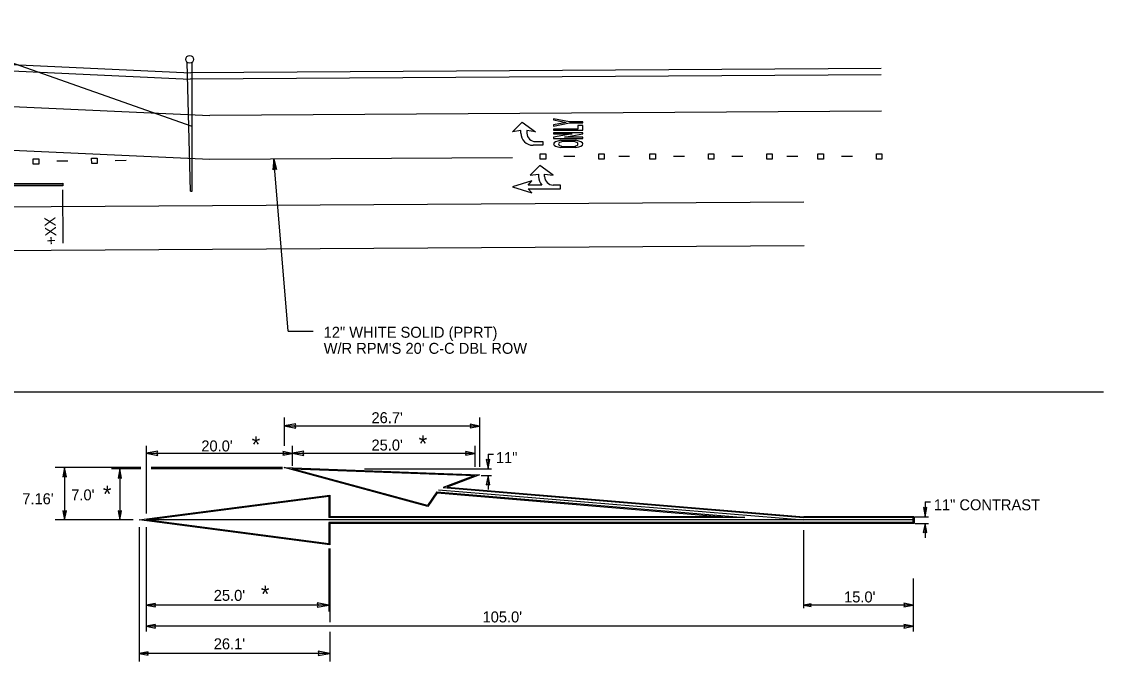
# Model space of a CAD drawing. Extents: x 538465 to 539103, y 1527987 to 1528392.
# Drawn here: x 538806.8 to 539102.9, y 1528140.9 to 1528316.1 of the extents above; entities that cross this region are included whole.
import ezdxf

# ---------------------------------------------------------------- set-up
doc = ezdxf.new("R2010")
doc.units = 0
for name, color, linetype in [('1', 7, 'Continuous'), ('CL_dp', 7, 'Continuous'), ('Default', 7, 'Continuous'), ('DimLines_dp', 7, 'Continuous'), ('DirArrowsPavt', 7, 'Continuous'), ('ImageAttachment_dp', 7, 'Continuous'), ('LeaderLine_dp', 7, 'Continuous'), ('PavtMessage', 7, 'Continuous'), ('PavtMiscMat', 7, 'Continuous'), ('PMStripe6W(10-30)', 7, 'Continuous'), ('TextLabel', 7, 'Continuous'), ('TextMajor', 7, 'Continuous')]:
    doc.layers.add(name, color=color, linetype=linetype)

msp = doc.modelspace()

# ---------------------------------------------------------------- linework, layer by layer
at = {"layer": '1'}
for p, q in [((538852.98, 1528269.7), (538852.08, 1528304.95)), ((538853.51, 1528269.71), (538853.51, 1528304.97)), ((538852.98, 1528269.7), (538853.51, 1528269.71))]:
    msp.add_line(p, q, dxfattribs=at)
msp.add_circle((538852.78, 1528305.76), 1.07, dxfattribs=at)
at = {"layer": 'CL_dp'}
for p, q in [((538611.16, 1528270.2), (538818.07, 1528271.49)), ((538920.87, 1528187.94), (539020.82, 1528179.64)), ((539050.87, 1528179.64), (538840.87, 1528179.64))]:
    msp.add_line(p, q, dxfattribs=at)
at = {"layer": 'Default'}
for p, q in [((538550.39, 1528316.09), (538853.15, 1528302.11)), ((538549.84, 1528314.35), (538852.95, 1528300.36)), ((538547.55, 1528304.74), (538858.35, 1528290.39)), ((538547.91, 1528292.72), (538858.28, 1528278.39)), ((539042.15, 1528291.54), (538858.35, 1528290.39)), ((538858.28, 1528278.39), (538941.21, 1528278.91)), ((538958.24, 1528279.14), (538955.24, 1528279.14)), ((538973.24, 1528279.14), (538970.24, 1528279.14)), ((538988.24, 1528279.14), (538985.24, 1528279.14)), ((539004.24, 1528279.14), (539001.24, 1528279.14)), ((539019.24, 1528279.14), (539016.24, 1528279.14)), ((539034.24, 1528279.14), (539031.24, 1528279.14)), ((538819.42, 1528277.88), (538816.42, 1528277.85)), ((538835.41, 1528278.06), (538832.41, 1528278.02))]:
    msp.add_line(p, q, dxfattribs=at)
for points in [[(538948.78, 1528279.89), (538950.28, 1528279.89), (538950.28, 1528278.39), (538948.78, 1528278.39)], [(538964.78, 1528279.89), (538966.28, 1528279.89), (538966.28, 1528278.39), (538964.78, 1528278.39)], [(538978.78, 1528279.89), (538980.28, 1528279.89), (538980.28, 1528278.39), (538978.78, 1528278.39)], [(538994.78, 1528279.89), (538996.28, 1528279.89), (538996.28, 1528278.39), (538994.78, 1528278.39)], [(539010.78, 1528279.89), (539012.28, 1528279.89), (539012.28, 1528278.39), (539010.78, 1528278.39)], [(539024.78, 1528279.89), (539026.28, 1528279.89), (539026.28, 1528278.39), (539024.78, 1528278.39)], [(539040.78, 1528279.89), (539042.28, 1528279.89), (539042.28, 1528278.39), (539040.78, 1528278.39)], [(538809.96, 1528278.54), (538811.46, 1528278.55), (538811.47, 1528277.05), (538809.97, 1528277.04)], [(538825.96, 1528278.71), (538827.46, 1528278.72), (538827.47, 1528277.22), (538825.97, 1528277.21)]]:
    msp.add_lwpolyline(points, close=True, dxfattribs=at)
at = {"layer": 'DimLines_dp'}
for p, q in [((538818.17, 1528255.41), (538818.08, 1528270.03)), ((538878.69, 1528207.72), (538878.69, 1528199.95)), ((538881.86, 1528206.01), (538878.69, 1528205.42)), ((538878.69, 1528205.42), (538881.86, 1528204.81)), ((538932.12, 1528205.36), (538878.69, 1528205.36)), ((538881.62, 1528205.42), (538881.86, 1528206.01)), ((538881.86, 1528204.81), (538881.62, 1528205.42)), ((538932.12, 1528205.36), (538929.58, 1528205.85)), ((538929.58, 1528205.85), (538929.77, 1528205.36)), ((538929.77, 1528205.36), (538929.58, 1528204.89)), ((538929.58, 1528204.89), (538932.12, 1528205.36)), ((538932.12, 1528207.72), (538932.12, 1528194.22)), ((538840.87, 1528199.95), (538840.87, 1528181.44)), ((538880.87, 1528199.95), (538880.87, 1528194.49)), ((538930.87, 1528199.95), (538930.87, 1528194.22)), ((538844.04, 1528198.52), (538840.87, 1528197.93)), ((538840.87, 1528197.93), (538844.04, 1528197.32)), ((538880.87, 1528197.87), (538840.87, 1528197.87)), ((538843.8, 1528197.93), (538844.04, 1528198.52)), ((538844.04, 1528197.32), (538843.8, 1528197.93)), ((538880.87, 1528197.87), (538878.33, 1528198.36)), ((538878.33, 1528198.36), (538878.53, 1528197.87)), ((538878.53, 1528197.87), (538878.33, 1528197.4)), ((538878.33, 1528197.4), (538880.87, 1528197.87)), ((538884.04, 1528198.52), (538880.87, 1528197.93)), ((538880.87, 1528197.93), (538884.04, 1528197.32)), ((538930.87, 1528197.87), (538880.87, 1528197.87)), ((538883.8, 1528197.93), (538884.04, 1528198.52)), ((538884.04, 1528197.32), (538883.8, 1528197.93)), ((538930.87, 1528197.87), (538928.34, 1528198.36)), ((538928.34, 1528198.36), (538928.53, 1528197.87)), ((538928.53, 1528197.87), (538928.34, 1528197.4)), ((538928.34, 1528197.4), (538930.87, 1528197.87)), ((538934.47, 1528195.98), (538934, 1528196.17)), ((538934, 1528196.17), (538934.47, 1528193.64)), ((538934.47, 1528197.7), (538934.47, 1528193.64)), ((538934.47, 1528197.7), (538935.96, 1528197.7)), ((538934.47, 1528193.64), (538934.96, 1528196.17)), ((538934.96, 1528196.17), (538934.47, 1528195.98)), ((538839.47, 1528193.97), (538815.94, 1528193.97)), ((538818.57, 1528193.97), (538818.08, 1528191.43)), ((538818.57, 1528193.97), (538818.57, 1528179.64)), ((538819.04, 1528191.43), (538818.57, 1528193.97)), ((538839.47, 1528193.64), (538831.36, 1528193.64)), ((538833.67, 1528193.64), (538833.18, 1528191.1)), ((538833.67, 1528193.64), (538833.67, 1528179.64)), ((538834.14, 1528191.1), (538833.67, 1528193.64)), ((538878.21, 1528193.97), (538842.24, 1528193.97)), ((538878.21, 1528193.64), (538842.24, 1528193.64)), ((538900.65, 1528193.64), (538935.38, 1528193.64)), ((538818.08, 1528191.43), (538818.57, 1528191.62)), ((538818.57, 1528191.62), (538819.04, 1528191.43)), ((538833.18, 1528191.1), (538833.67, 1528191.29)), ((538833.67, 1528191.29), (538834.14, 1528191.1)), ((538932.59, 1528191.8), (538935.38, 1528191.8)), ((538934.47, 1528191.8), (538933.98, 1528189.27)), ((538934.47, 1528191.8), (538934.47, 1528187.95)), ((538934.95, 1528189.27), (538934.47, 1528191.8)), ((538933.98, 1528189.27), (538934.47, 1528189.46)), ((538934.47, 1528189.46), (538934.95, 1528189.27)), ((539054.11, 1528184.61), (539054.11, 1528180.55)), ((539054.11, 1528184.61), (539055.6, 1528184.61)), ((538818.57, 1528181.98), (538818.1, 1528182.17)), ((538818.1, 1528182.17), (538818.57, 1528179.64)), ((538818.57, 1528179.64), (538819.06, 1528182.17)), ((538819.06, 1528182.17), (538818.57, 1528181.98)), ((538833.67, 1528181.98), (538833.2, 1528182.17)), ((538833.2, 1528182.17), (538833.67, 1528179.64)), ((538833.67, 1528179.64), (538834.16, 1528182.17)), ((538834.16, 1528182.17), (538833.67, 1528181.98)), ((539054.11, 1528182.9), (539053.64, 1528183.09)), ((539053.64, 1528183.09), (539054.11, 1528180.55)), ((539054.11, 1528180.55), (539054.6, 1528183.09)), ((539054.6, 1528183.09), (539054.11, 1528182.9)), ((538837.36, 1528179.64), (538815.94, 1528179.64)), ((539051.38, 1528180.55), (539055.02, 1528180.55)), ((539051.38, 1528178.72), (539055.02, 1528178.72)), ((539054.1, 1528178.72), (539053.61, 1528176.18)), ((539054.57, 1528176.18), (539054.1, 1528178.72)), ((539054.11, 1528178.72), (539054.11, 1528174.77)), ((538838.93, 1528177.69), (538838.93, 1528140.93)), ((538840.87, 1528177.69), (538840.87, 1528149.11)), ((539020.87, 1528176.82), (539020.87, 1528155.52)), ((539053.61, 1528176.18), (539054.1, 1528176.37)), ((539054.1, 1528176.37), (539054.57, 1528176.18)), ((538890.87, 1528171.87), (538890.87, 1528154.63)), ((538891.12, 1528171.87), (538891.12, 1528151.63)), ((539050.87, 1528163.65), (539050.87, 1528149.11)), ((538843.41, 1528156.82), (538840.87, 1528156.35)), ((538890.87, 1528156.35), (538840.87, 1528156.35)), ((538840.87, 1528156.35), (538843.41, 1528155.86)), ((538843.22, 1528156.35), (538843.41, 1528156.82)), ((538843.41, 1528155.86), (538843.22, 1528156.35)), ((538890.87, 1528156.35), (538887.7, 1528156.96)), ((538887.7, 1528156.96), (538887.94, 1528156.35)), ((538887.94, 1528156.35), (538887.7, 1528155.76)), ((538887.7, 1528155.76), (538890.87, 1528156.35)), ((539022.9, 1528156.73), (539020.87, 1528156.35)), ((539050.87, 1528156.35), (539020.87, 1528156.35)), ((539020.87, 1528156.35), (539022.9, 1528155.96)), ((539022.75, 1528156.35), (539022.9, 1528156.73)), ((539022.9, 1528155.96), (539022.75, 1528156.35)), ((539050.87, 1528156.35), (539048.33, 1528156.84)), ((539048.33, 1528156.84), (539048.53, 1528156.35)), ((539048.53, 1528156.35), (539048.33, 1528155.88)), ((539048.33, 1528155.88), (539050.87, 1528156.35)), ((538843.41, 1528151.02), (538840.87, 1528150.54)), ((539050.87, 1528150.54), (538840.87, 1528150.54)), ((538840.87, 1528150.54), (538843.41, 1528150.05)), ((538843.22, 1528150.54), (538843.41, 1528151.02)), ((538843.41, 1528150.05), (538843.22, 1528150.54)), ((538891.12, 1528148.99), (538891.12, 1528140.93)), ((539050.87, 1528150.54), (539048.33, 1528151.03)), ((539048.33, 1528151.03), (539048.53, 1528150.54)), ((539048.53, 1528150.54), (539048.33, 1528150.07)), ((539048.33, 1528150.07), (539050.87, 1528150.54)), ((538841.47, 1528143.57), (538838.93, 1528143.09)), ((538891.12, 1528143.09), (538838.93, 1528143.09)), ((538838.93, 1528143.09), (538841.47, 1528142.6)), ((538841.28, 1528143.09), (538841.47, 1528143.57)), ((538841.47, 1528142.6), (538841.28, 1528143.09)), ((538891.12, 1528143.09), (538887.95, 1528143.71)), ((538887.95, 1528143.71), (538888.19, 1528143.09)), ((538888.19, 1528143.09), (538887.95, 1528142.5)), ((538887.95, 1528142.5), (538891.12, 1528143.09))]:
    msp.add_line(p, q, dxfattribs=at)
at = {"layer": 'DirArrowsPavt'}
for p, q in [((538941.21, 1528285.91), (538943.79, 1528288.57)), ((538943.79, 1528288.57), (538947.46, 1528285.91)), ((538943.46, 1528286.24), (538941.21, 1528285.91)), ((538943.46, 1528285.57), (538943.46, 1528286.24)), ((538947.46, 1528285.91), (538945.12, 1528286.24)), ((538945.12, 1528286.24), (538945.12, 1528285.57)), ((538949.46, 1528282.24), (538946.79, 1528282.24)), ((538947.46, 1528283.24), (538949.46, 1528283.24)), ((538949.46, 1528283.24), (538949.46, 1528282.24)), ((538948.62, 1528276.68), (538946.04, 1528274.02)), ((538952.29, 1528274.02), (538948.62, 1528276.68)), ((538946.04, 1528274.02), (538948.29, 1528274.35)), ((538948.29, 1528274.35), (538948.29, 1528273.68)), ((538949.96, 1528274.35), (538952.29, 1528274.02)), ((538949.96, 1528273.68), (538949.96, 1528274.35)), ((538818.07, 1528271.17), (538738.07, 1528270.67)), ((538803.08, 1528271.75), (538818.06, 1528271.84)), ((538818.06, 1528271.84), (538818.07, 1528271.17)), ((538946.46, 1528272.52), (538941.21, 1528270.85)), ((538941.21, 1528270.85), (538946.46, 1528269.18)), ((538945.46, 1528271.35), (538946.46, 1528272.52)), ((538949.24, 1528271.35), (538945.46, 1528271.35)), ((538946.46, 1528269.18), (538945.46, 1528270.35)), ((538945.46, 1528270.35), (538954.29, 1528270.35)), ((538954.29, 1528271.35), (538952.29, 1528271.35)), ((538954.29, 1528270.35), (538954.29, 1528271.35))]:
    msp.add_line(p, q, dxfattribs=at)
for centre, radius, end in [((538946.79, 1528285.57), 3.33, 270), ((538947.46, 1528285.57), 2.33, 270), ((538951.62, 1528273.68), 3.33, 224.427), ((538952.29, 1528273.68), 2.33, 270)]:
    msp.add_arc(centre, radius, 180, end, dxfattribs=at)
at = {"layer": 'ImageAttachment_dp'}
for p, q in [((539042.07, 1528303.29), (538853.15, 1528302.11)), ((539042.08, 1528301.54), (538852.95, 1528300.36))]:
    msp.add_line(p, q, dxfattribs=at)
at = {"layer": 'LeaderLine_dp'}
for p, q in [((538853.51, 1528287.34), (538789.22, 1528310.05)), ((538875.79, 1528278.5), (538875.53, 1528275.55)), ((538875.79, 1528278.5), (538875.78, 1528275.69)), ((538879.77, 1528231.38), (538875.79, 1528278.5)), ((538875.79, 1528278.5), (538876.55, 1528275.64)), ((538875.79, 1528278.5), (538876.27, 1528275.73)), ((538876.02, 1528275.82), (538875.53, 1528275.55)), ((538876.55, 1528275.64), (538876.02, 1528275.82)), ((538879.77, 1528231.38), (538886.63, 1528231.38))]:
    msp.add_line(p, q, dxfattribs=at)
at = {"layer": 'PavtMessage'}
for p, q in [((538956.76, 1528288.67), (538952.43, 1528289.5)), ((538952.43, 1528289.5), (538952.43, 1528289.16)), ((538952.43, 1528289.16), (538955.86, 1528288.5)), ((538955.86, 1528288.5), (538952.43, 1528287.84)), ((538952.43, 1528287.5), (538956.76, 1528288.34)), ((538952.43, 1528287.84), (538952.43, 1528287.5)), ((538960.43, 1528288.67), (538956.76, 1528288.67)), ((538956.76, 1528288.34), (538960.43, 1528288.34)), ((538960.43, 1528288.34), (538960.43, 1528288.67)), ((538959.1, 1528286.67), (538952.43, 1528286.67)), ((538952.43, 1528286.67), (538952.43, 1528286.34)), ((538952.43, 1528286.34), (538960.43, 1528286.34)), ((538960.43, 1528285.67), (538952.43, 1528285.67)), ((538952.43, 1528285.67), (538952.43, 1528285.34)), ((538952.43, 1528285.34), (538957.53, 1528285.34)), ((538957.53, 1528285.34), (538952.43, 1528284.42)), ((538955.43, 1528284.42), (538960.43, 1528285.34)), ((538960.43, 1528287.67), (538959.1, 1528287.67)), ((538959.1, 1528287.67), (538959.1, 1528286.67)), ((538960.43, 1528286.34), (538960.43, 1528287.67)), ((538960.43, 1528285.34), (538960.43, 1528285.67)), ((538952.43, 1528284.42), (538952.43, 1528284.09)), ((538952.43, 1528284.09), (538960.43, 1528284.09)), ((538954.37, 1528283.59), (538958.49, 1528283.59)), ((538958.03, 1528283.25), (538954.83, 1528283.25)), ((538954.83, 1528281.92), (538958.03, 1528281.92)), ((538960.43, 1528284.42), (538955.43, 1528284.42)), ((538960.43, 1528284.09), (538960.43, 1528284.42)), ((538958.49, 1528281.59), (538954.37, 1528281.59))]:
    msp.add_line(p, q, dxfattribs=at)
for major_axis, ratio, start_param, end_param in [((-4, 0), 0.291667, 5.253489, 7.312882), ((-2.67, 0), 0.3125, 5.35589, 7.210481), ((-2.67, 0), 0.3125, 2.214297, 4.068888), ((-4, 0), 0.291667, 2.111896, 4.171289)]:
    msp.add_ellipse((538956.43, 1528282.59), major_axis=major_axis, ratio=ratio, start_param=start_param, end_param=end_param, dxfattribs=at)
at = {"layer": 'PavtMiscMat'}
for p, q in [((538917.98, 1528183.35), (538878.69, 1528193.97)), ((538878.69, 1528193.97), (538932.12, 1528192.01)), ((538917.87, 1528183.64), (538880.87, 1528193.64)), ((538880.87, 1528193.64), (538930.87, 1528191.8)), ((538917.87, 1528183.64), (538880.87, 1528193.64)), ((538880.87, 1528193.64), (538930.87, 1528191.8)), ((538930.87, 1528191.8), (538922.16, 1528188.5)), ((538930.87, 1528191.8), (538922.16, 1528188.5)), ((538932.12, 1528192.01), (538923.28, 1528188.66)), ((538920.43, 1528187.31), (538917.87, 1528183.64)), ((538920.43, 1528187.31), (538917.87, 1528183.64)), ((538920.43, 1528187.31), (539004.77, 1528180.3)), ((538920.43, 1528187.31), (539004.77, 1528180.3)), ((538922.16, 1528188.5), (539020.87, 1528180.3)), ((538922.16, 1528188.5), (539020.87, 1528180.3)), ((538923.28, 1528188.66), (539020.88, 1528180.55)), ((538838.93, 1528179.64), (538891.12, 1528186.42)), ((538840.87, 1528179.64), (538890.87, 1528186.14)), ((538840.87, 1528179.64), (538890.87, 1528186.14)), ((538890.87, 1528186.14), (538890.87, 1528180.3)), ((538890.87, 1528186.14), (538890.87, 1528180.3)), ((538891.12, 1528186.42), (538891.12, 1528180.55)), ((538920.55, 1528187.05), (538917.98, 1528183.35)), ((538920.55, 1528187.05), (538998.74, 1528180.55)), ((538891.12, 1528172.85), (538838.93, 1528179.64)), ((538890.87, 1528173.14), (538840.87, 1528179.64)), ((538890.87, 1528173.14), (538840.87, 1528179.64)), ((539004.77, 1528180.3), (538890.87, 1528180.3)), ((539004.77, 1528180.3), (538890.87, 1528180.3)), ((538890.87, 1528178.97), (538890.87, 1528173.14)), ((539050.87, 1528178.97), (538890.87, 1528178.97)), ((538890.87, 1528178.97), (538890.87, 1528173.14)), ((539050.87, 1528178.97), (538890.87, 1528178.97)), ((538998.74, 1528180.55), (538891.12, 1528180.55)), ((539051.12, 1528178.72), (538891.12, 1528178.72)), ((538891.12, 1528178.72), (538891.12, 1528172.85)), ((539050.87, 1528180.3), (539020.87, 1528180.3)), ((539050.87, 1528180.3), (539020.87, 1528180.3)), ((539051.12, 1528180.55), (539020.88, 1528180.55)), ((539025.94, 1528180.55), (539050.87, 1528180.55)), ((539025.94, 1528180.55), (539050.87, 1528180.55)), ((539050.87, 1528180.3), (539050.87, 1528178.97)), ((539050.87, 1528178.97), (539050.87, 1528180.3)), ((539050.87, 1528180.3), (539050.87, 1528178.97)), ((539050.87, 1528178.97), (539050.87, 1528180.3)), ((539051.12, 1528180.55), (539051.12, 1528178.72))]:
    msp.add_line(p, q, dxfattribs=at)
msp.add_lwpolyline([(539051, 1528180.3), (539050.87, 1528180.3), (539050.87, 1528178.97), (539051, 1528178.97)], close=True, dxfattribs=at)
at = {"layer": 'PMStripe6W(10-30)'}
for p, q in [((538571.06, 1528263.95), (539020.96, 1528266.76)), ((538571.13, 1528251.96), (539021.04, 1528254.76))]:
    msp.add_line(p, q, dxfattribs=at)
at = {"layer": 'TextMajor'}
msp.add_line((538486.92, 1528214.71), (539102.92, 1528214.71), dxfattribs=at)

# ---------------------------------------------------------------- texts
at = {"layer": 'DimLines_dp'}
msp.add_text('+XX', height=3, rotation=92.6209, dxfattribs=at).set_placement((538816.38, 1528255.03))
for s, height, p in [("26.7'", 3, (538902.57, 1528206.15)), ('*', 4.5, (538869.77, 1528198.06)), ('*', 4.5, (538915.48, 1528198.3)), ("20.0'", 3, (538855.99, 1528198.42)), ("25.0'", 3, (538902.57, 1528198.66)), ('11"', 3, (538936.63, 1528195.22)), ("7.0'", 3, (538820.38, 1528185.02)), ('*', 4.5, (538829.05, 1528184.52)), ("7.16'", 3, (538806.98, 1528183.95)), ('11" CONTRAST', 3, (539056.51, 1528182.3)), ("25.0'", 3, (538859.39, 1528157.5)), ('*', 4.5, (538872.3, 1528157.14)), ("15.0'", 3, (539031.94, 1528157.08)), ("105.0'", 3, (538932.97, 1528151.6)), ("26.1'", 3, (538859.39, 1528144.24))]:
    msp.add_text(s, height=height, dxfattribs=at).set_placement(p)
at = {"layer": 'TextLabel'}
for s, p in [('12" WHITE SOLID (PPRT)', (538889.48, 1528229.54)), ("W/R RPM'S 20' C-C DBL ROW", (538889.48, 1528225.14))]:
    msp.add_text(s, height=3, dxfattribs=at).set_placement(p)

doc.saveas('drawing.dxf')
